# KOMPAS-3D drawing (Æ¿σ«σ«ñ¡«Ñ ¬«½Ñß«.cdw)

Referenced files in D:\Мои документы - Дмитрий\Чертежи Компас\: Тихоходное колесо.cdw
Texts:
  Колесо зубчатое
  Яковлев Д.А.
  Курсовая по деталям машин.
  125 1 126 1 127 1 128 0 50 1|SPDS|125 1 126 1 127 1 128 0 50 1
  129 1 130 1 131 1 132 0 50 1|SPDS|129 1 130 1 131 1 132 0 50 1
  Rz 40
  Rz 20
  Ra 2,5
  Модуль
  Число зубьев
  Угол наклона зубьев
  Symbol type A
  Нормальный исходный контур
  ГОСТ 13755-81
  Коэффициент смещения
  Степень точности по ГОСТ 1643-81
  Длина общей нормали
  Делительный диаметр
  Обозначение чертежа сопря-
  гаемой зубчатой шестерни
  ДМ 09.05.01.00.011
  Js9( 0,021)
  Js9
  HB 270.
  Rz 80
  Сталь 45 ГОСТ 1050-88
  ДГТУ
  ККП-31
Dimensions and other numbers on the sheet: 177,5; 283,28; 100,; 60; 6 отв.; 250; 105; 255; 17; 72; 0,5; 2 фаски; 1; 2,5; 207; 16; 0; 8-7-7-В; 103,83 -0,18 -0,28; 278,28; 65; 69,4; 18; 0,1; 0,025; 1:2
